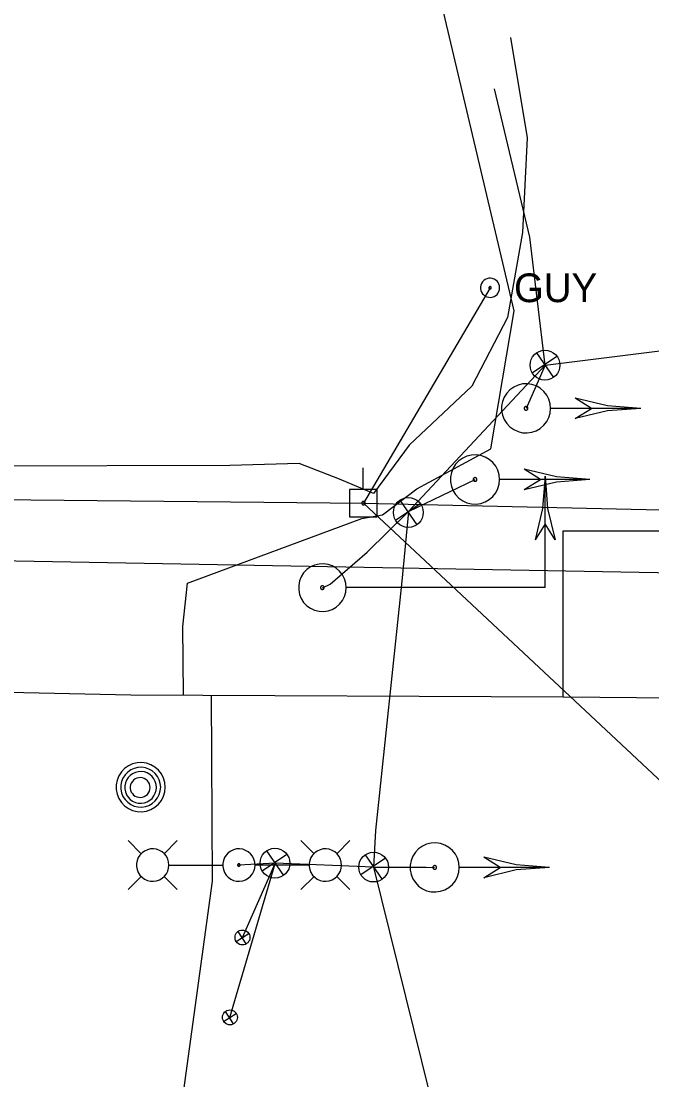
# Model space of a CAD drawing. Extents: x 600849 to 606371, y 330010 to 403088.
# Drawn here: x 604922.6 to 605007.3, y 349901.2 to 350043.3 of the extents above; entities that cross this region are included whole.
import ezdxf

# ---------------------------------------------------------------- set-up
doc = ezdxf.new("R2010")
doc.units = 0
for name, color, linetype in [('E_LTG', 7, 'Continuous'), ('E_LTG_CID', 7, 'Continuous'), ('E_SIG', 7, 'Continuous'), ('E_SIG_Conduit', 7, 'Continuous'), ('E_UTL_E_UG', 7, 'Continuous'), ('E_UTL_EGuyWire', 7, 'Continuous'), ('E_UTL_EPowerPole', 7, 'Continuous'), ('E_UTL_G_UG', 7, 'Continuous'), ('E_UTL_Loop_UG', 7, 'Continuous'), ('E_UTL_MH', 7, 'Continuous'), ('E_UTL_Overhead', 7, 'Continuous'), ('E_UTL_SAN_UG', 7, 'Continuous'), ('E_UTL_TV_UG', 7, 'Continuous')]:
    doc.layers.add(name, color=color, linetype=linetype)

# ---------------------------------------------------------------- blocks, each defined once
blk = doc.blocks.new('_U350')
at = {"layer": 'E_SIG'}
for p, q in [((0, 6.1), (0, -6.1)), ((-6.09, 0.4), (6.1, 0.4))]:
    blk.add_line(p, q, dxfattribs=at)
blk.add_circle((0, 0.01), 6.1, dxfattribs=at)
blk = doc.blocks.new('_U351')
at = {"layer": 'E_SIG'}
for p, q in [((0, 6.1), (0, -6.1)), ((-6.09, 0.4), (6.1, 0.4))]:
    blk.add_line(p, q, dxfattribs=at)
blk.add_circle((0, 0.01), 6.1, dxfattribs=at)
blk = doc.blocks.new('_U358')
at = {"layer": 'E_SIG'}
for p, q in [((0, 6.1), (0, -6.1)), ((-6.09, 0.4), (6.1, 0.4))]:
    blk.add_line(p, q, dxfattribs=at)
blk.add_circle((0, 0.01), 6.1, dxfattribs=at)
blk = doc.blocks.new('_U359')
at = {"layer": 'E_SIG'}
for p, q in [((0, 6.1), (0, -6.1)), ((-6.09, 0.4), (6.1, 0.4))]:
    blk.add_line(p, q, dxfattribs=at)
blk.add_circle((0, 0.01), 6.1, dxfattribs=at)
blk = doc.blocks.new('_U360')
at = {"layer": 'E_SIG'}
for p, q in [((-6.09, 0.4), (6.1, 0.4)), ((0, 6.1), (0, -6.1))]:
    blk.add_line(p, q, dxfattribs=at)
blk.add_circle((0, 0.01), 6.1, dxfattribs=at)
blk = doc.blocks.new('_U361')
at = {"layer": 'E_SIG'}
for p, q in [((-6.09, 0.4), (6.1, 0.4)), ((0, 6.1), (0, -6.1))]:
    blk.add_line(p, q, dxfattribs=at)
blk.add_circle((0, 0.01), 6.1, dxfattribs=at)

msp = doc.modelspace()

# ---------------------------------------------------------------- linework, layer by layer
at = {"layer": 'E_LTG'}
for points in [[(604938.74, 349931.53), (604936.97, 349933.3)], [(604941.79, 349931.53), (604943.57, 349933.3)], [(604961.92, 349931.53), (604960.14, 349933.3)], [(604964.96, 349931.53), (604966.74, 349933.3)], [(604942.44, 349930), (604942.4, 349930.42), (604942.29, 349930.81), (604942.1, 349931.18), (604941.84, 349931.5), (604941.53, 349931.78), (604941.17, 349931.98), (604940.78, 349932.12), (604940.37, 349932.18), (604939.96, 349932.16), (604939.56, 349932.06), (604939.18, 349931.89), (604938.84, 349931.65), (604938.56, 349931.35), (604938.33, 349931), (604938.18, 349930.62), (604938.1, 349930.21), (604938.1, 349929.8), (604938.18, 349929.39), (604938.33, 349929.01), (604938.56, 349928.66), (604938.84, 349928.36), (604939.18, 349928.12), (604939.56, 349927.95), (604939.96, 349927.85), (604940.37, 349927.83), (604940.78, 349927.89), (604941.17, 349928.02), (604941.53, 349928.23), (604941.84, 349928.5), (604942.1, 349928.83), (604942.29, 349929.19), (604942.4, 349929.59), (604942.44, 349930)], [(604954.01, 349930), (604953.97, 349930.41), (604953.85, 349930.81), (604953.66, 349931.18), (604953.41, 349931.5), (604953.1, 349931.78), (604952.74, 349931.98), (604952.35, 349932.12), (604951.94, 349932.18), (604951.52, 349932.16), (604951.12, 349932.06), (604950.75, 349931.89), (604950.41, 349931.65), (604950.12, 349931.35), (604949.9, 349931), (604949.75, 349930.62), (604949.67, 349930.21), (604949.67, 349929.8), (604949.75, 349929.39), (604949.9, 349929.01), (604950.12, 349928.66), (604950.41, 349928.36), (604950.75, 349928.12), (604951.12, 349927.95), (604951.52, 349927.85), (604951.94, 349927.83), (604952.35, 349927.89), (604952.74, 349928.02), (604953.1, 349928.23), (604953.41, 349928.5), (604953.66, 349928.83), (604953.85, 349929.19), (604953.97, 349929.59), (604954.01, 349930)], [(604965.61, 349930), (604965.57, 349930.41), (604965.46, 349930.81), (604965.27, 349931.18), (604965.01, 349931.5), (604964.7, 349931.78), (604964.34, 349931.98), (604963.95, 349932.12), (604963.54, 349932.18), (604963.13, 349932.16), (604962.73, 349932.06), (604962.35, 349931.89), (604962.01, 349931.65), (604961.73, 349931.35), (604961.5, 349931), (604961.35, 349930.62), (604961.27, 349930.21), (604961.27, 349929.8), (604961.35, 349929.39), (604961.5, 349929.01), (604961.73, 349928.66), (604962.01, 349928.36), (604962.35, 349928.12), (604962.73, 349927.95), (604963.13, 349927.85), (604963.54, 349927.83), (604963.95, 349927.89), (604964.34, 349928.02), (604964.7, 349928.23), (604965.01, 349928.5), (604965.27, 349928.83), (604965.46, 349929.19), (604965.57, 349929.59), (604965.61, 349930)], [(604942.48, 349930), (604949.66, 349930)], [(604952, 349930), (604952, 349930.03), (604951.99, 349930.06), (604951.97, 349930.09), (604951.95, 349930.12), (604951.93, 349930.14), (604951.9, 349930.15), (604951.87, 349930.16), (604951.84, 349930.17), (604951.81, 349930.17), (604951.78, 349930.16), (604951.75, 349930.15), (604951.73, 349930.13), (604951.7, 349930.11), (604951.69, 349930.08), (604951.67, 349930.05), (604951.67, 349930.02), (604951.67, 349929.99), (604951.67, 349929.96), (604951.69, 349929.93), (604951.7, 349929.9), (604951.73, 349929.88), (604951.75, 349929.86), (604951.78, 349929.85), (604951.81, 349929.84), (604951.84, 349929.84), (604951.87, 349929.84), (604951.9, 349929.85), (604951.93, 349929.87), (604951.95, 349929.89), (604951.97, 349929.91), (604951.99, 349929.94), (604952, 349929.97), (604952, 349930)], [(604961.22, 349930), (604954.05, 349930)], [(604938.74, 349928.48), (604936.97, 349926.7)], [(604941.79, 349928.48), (604943.57, 349926.7)], [(604961.92, 349928.48), (604960.14, 349926.7)], [(604964.96, 349928.48), (604966.74, 349926.7)]]:
    msp.add_lwpolyline(points, dxfattribs=at)
at = {"layer": 'E_LTG_CID'}
msp.add_lwpolyline([(604956.7, 349930.25), (604951.83, 349930)], dxfattribs=at)
at = {"layer": 'E_SIG'}
for points in [[(604993.68, 349991.33), (604993.62, 349991.95), (604993.44, 349992.56), (604993.15, 349993.11), (604992.76, 349993.61), (604992.29, 349994.02), (604991.75, 349994.33), (604991.15, 349994.54), (604990.53, 349994.63), (604989.91, 349994.6), (604989.3, 349994.45), (604988.73, 349994.19), (604988.21, 349993.82), (604987.78, 349993.37), (604987.44, 349992.84), (604987.21, 349992.26), (604987.09, 349991.64), (604987.09, 349991.02), (604987.21, 349990.4), (604987.44, 349989.82), (604987.78, 349989.29), (604988.21, 349988.84), (604988.73, 349988.47), (604989.3, 349988.21), (604989.91, 349988.06), (604990.53, 349988.03), (604991.15, 349988.12), (604991.75, 349988.33), (604992.29, 349988.64), (604992.76, 349989.05), (604993.15, 349989.55), (604993.44, 349990.1), (604993.62, 349990.7), (604993.68, 349991.33)], [(604999.18, 349991.33), (604996.98, 349992.71)], [(605005.78, 349991.33), (605001.32, 349991.68), (604996.98, 349992.7)], [(604990.63, 349991.33), (604990.62, 349991.38), (604990.61, 349991.42), (604990.59, 349991.47), (604990.56, 349991.5), (604990.52, 349991.54), (604990.48, 349991.56), (604990.44, 349991.57), (604990.39, 349991.58), (604990.34, 349991.58), (604990.29, 349991.57), (604990.25, 349991.55), (604990.21, 349991.52), (604990.18, 349991.49), (604990.15, 349991.45), (604990.13, 349991.4), (604990.12, 349991.35), (604990.12, 349991.31), (604990.13, 349991.26), (604990.15, 349991.21), (604990.18, 349991.17), (604990.21, 349991.14), (604990.25, 349991.11), (604990.29, 349991.09), (604990.34, 349991.08), (604990.39, 349991.08), (604990.44, 349991.08), (604990.48, 349991.1), (604990.52, 349991.12), (604990.56, 349991.16), (604990.59, 349991.19), (604990.61, 349991.24), (604990.62, 349991.28), (604990.63, 349991.33)], [(605005.78, 349991.33), (604993.73, 349991.33)], [(605005.78, 349991.33), (605001.32, 349990.98), (604996.98, 349989.95)], [(604996.98, 349989.96), (604999.18, 349991.33)], [(604986.83, 349981.78), (604986.77, 349982.4), (604986.59, 349983.01), (604986.3, 349983.56), (604985.92, 349984.06), (604985.44, 349984.47), (604984.9, 349984.78), (604984.3, 349984.99), (604983.68, 349985.07), (604983.06, 349985.04), (604982.45, 349984.9), (604981.88, 349984.64), (604981.37, 349984.27), (604980.93, 349983.82), (604980.59, 349983.29), (604980.36, 349982.71), (604980.24, 349982.09), (604980.24, 349981.46), (604980.36, 349980.85), (604980.59, 349980.27), (604980.93, 349979.74), (604981.37, 349979.28), (604981.88, 349978.92), (604982.45, 349978.66), (604983.06, 349978.51), (604983.68, 349978.48), (604984.3, 349978.57), (604984.9, 349978.78), (604985.44, 349979.09), (604985.92, 349979.5), (604986.3, 349979.99), (604986.59, 349980.55), (604986.77, 349981.15), (604986.83, 349981.78)], [(604998.93, 349981.78), (604994.47, 349982.12), (604990.13, 349983.15)], [(604992.33, 349981.78), (604990.13, 349983.15)], [(604992.94, 349982.2), (604992.6, 349977.88), (604991.6, 349973.66)], [(604992.94, 349967.26), (604992.94, 349982.2)], [(604992.94, 349982.2), (604993.27, 349977.88), (604994.27, 349973.66)], [(604983.78, 349981.78), (604983.77, 349981.83), (604983.76, 349981.87), (604983.74, 349981.91), (604983.71, 349981.95), (604983.67, 349981.98), (604983.63, 349982.01), (604983.59, 349982.02), (604983.54, 349982.03), (604983.49, 349982.03), (604983.44, 349982.02), (604983.4, 349982), (604983.36, 349981.97), (604983.33, 349981.93), (604983.3, 349981.89), (604983.28, 349981.85), (604983.28, 349981.8), (604983.28, 349981.75), (604983.28, 349981.71), (604983.3, 349981.66), (604983.33, 349981.62), (604983.36, 349981.59), (604983.4, 349981.56), (604983.44, 349981.54), (604983.49, 349981.53), (604983.54, 349981.53), (604983.59, 349981.53), (604983.63, 349981.55), (604983.67, 349981.57), (604983.71, 349981.6), (604983.74, 349981.64), (604983.76, 349981.68), (604983.77, 349981.73), (604983.78, 349981.78)], [(604998.93, 349981.78), (604986.88, 349981.78)], [(604998.93, 349981.78), (604994.47, 349981.43), (604990.13, 349980.4)], [(604990.13, 349980.41), (604992.33, 349981.78)], [(604992.94, 349975.8), (604991.6, 349973.66)], [(604994.27, 349973.66), (604992.94, 349975.8)], [(604966.25, 349967.25), (604966.19, 349967.86), (604966.02, 349968.44), (604965.74, 349968.99), (604965.36, 349969.46), (604964.9, 349969.86), (604964.37, 349970.17), (604963.8, 349970.37), (604963.2, 349970.45), (604962.59, 349970.42), (604962, 349970.28), (604961.44, 349970.03), (604960.95, 349969.68), (604960.53, 349969.23), (604960.2, 349968.72), (604959.97, 349968.16), (604959.86, 349967.56), (604959.86, 349966.95), (604959.97, 349966.35), (604960.2, 349965.79), (604960.53, 349965.27), (604960.95, 349964.83), (604961.44, 349964.48), (604962, 349964.23), (604962.59, 349964.08), (604963.2, 349964.06), (604963.8, 349964.14), (604964.37, 349964.34), (604964.9, 349964.65), (604965.36, 349965.04), (604965.74, 349965.52), (604966.02, 349966.06), (604966.19, 349966.65), (604966.25, 349967.25)], [(604963.29, 349967.25), (604963.28, 349967.3), (604963.27, 349967.35), (604963.25, 349967.39), (604963.22, 349967.42), (604963.19, 349967.45), (604963.15, 349967.48), (604963.1, 349967.49), (604963.06, 349967.5), (604963.01, 349967.5), (604962.96, 349967.49), (604962.92, 349967.47), (604962.88, 349967.44), (604962.85, 349967.41), (604962.83, 349967.37), (604962.81, 349967.32), (604962.8, 349967.28), (604962.8, 349967.23), (604962.81, 349967.19), (604962.83, 349967.14), (604962.85, 349967.1), (604962.88, 349967.07), (604962.92, 349967.04), (604962.96, 349967.02), (604963.01, 349967.01), (604963.06, 349967.01), (604963.1, 349967.02), (604963.15, 349967.03), (604963.19, 349967.05), (604963.22, 349967.09), (604963.25, 349967.12), (604963.27, 349967.16), (604963.28, 349967.21), (604963.29, 349967.25)], [(604992.94, 349967.26), (604966.3, 349967.26)], [(604985.46, 349967.26), (604985.46, 349967.26)], [(604981.41, 349929.68), (604981.35, 349930.31), (604981.18, 349930.91), (604980.89, 349931.47), (604980.5, 349931.96), (604980.03, 349932.37), (604979.48, 349932.68), (604978.89, 349932.89), (604978.27, 349932.98), (604977.64, 349932.95), (604977.03, 349932.8), (604976.46, 349932.54), (604975.95, 349932.18), (604975.52, 349931.72), (604975.18, 349931.19), (604974.95, 349930.61), (604974.83, 349930), (604974.83, 349929.37), (604974.95, 349928.75), (604975.18, 349928.17), (604975.52, 349927.64), (604975.95, 349927.19), (604976.46, 349926.82), (604977.03, 349926.56), (604977.64, 349926.42), (604978.27, 349926.39), (604978.89, 349926.48), (604979.48, 349926.68), (604980.03, 349926.99), (604980.5, 349927.41), (604980.89, 349927.9), (604981.18, 349928.46), (604981.35, 349929.06), (604981.41, 349929.68)], [(604993.51, 349929.68), (604989.06, 349930.03), (604984.71, 349931.06)], [(604986.91, 349929.68), (604984.71, 349931.06)], [(604978.37, 349929.68), (604978.36, 349929.73), (604978.35, 349929.78), (604978.33, 349929.82), (604978.3, 349929.86), (604978.26, 349929.89), (604978.22, 349929.91), (604978.17, 349929.93), (604978.13, 349929.93), (604978.08, 349929.93), (604978.03, 349929.92), (604977.99, 349929.9), (604977.95, 349929.87), (604977.92, 349929.84), (604977.89, 349929.8), (604977.87, 349929.75), (604977.86, 349929.71), (604977.86, 349929.66), (604977.87, 349929.61), (604977.89, 349929.57), (604977.92, 349929.53), (604977.95, 349929.49), (604977.99, 349929.46), (604978.03, 349929.44), (604978.08, 349929.43), (604978.13, 349929.43), (604978.17, 349929.44), (604978.22, 349929.45), (604978.26, 349929.48), (604978.3, 349929.51), (604978.33, 349929.55), (604978.35, 349929.59), (604978.36, 349929.63), (604978.37, 349929.68)], [(604993.51, 349929.68), (604981.47, 349929.68)], [(604993.51, 349929.68), (604989.06, 349929.34), (604984.71, 349928.31)], [(604984.71, 349928.31), (604986.91, 349929.68)]]:
    msp.add_lwpolyline(points, dxfattribs=at)
at = {"layer": 'E_SIG_Conduit'}
for points in [[(604992.92, 349997.12), (605041.26, 350003.17), (605045.68, 350004), (605067.59, 350003.14), (605103.15, 349993.06), (605106.99, 349992.73)], [(604963.04, 349967.25), (604964.1, 349967.7), (604969.04, 349972.01), (604974.59, 349977.47), (604992.92, 349997.12)], [(604992.92, 349997.12), (604990.38, 349991.33)], [(604974.59, 349977.47), (604983.53, 349981.78)], [(604974.59, 349977.47), (604973.7, 349968.11), (604970.17, 349934.65), (604969.92, 349929.73)], [(604969.92, 349929.73), (604956.7, 349930.25)], [(604969.92, 349929.73), (604985.98, 349864.78), (604987.57, 349858.81)], [(604969.92, 349929.73), (604976.98, 349929.73), (604978.11, 349929.68)]]:
    msp.add_lwpolyline(points, dxfattribs=at)
at = {"layer": 'E_UTL_E_UG'}
msp.add_lwpolyline([(604992.92, 349997.12), (604990.88, 350014.31), (604986.13, 350034.21)], dxfattribs=at)
at = {"layer": 'E_UTL_EGuyWire'}
msp.add_line((604985.55, 350007.51), (604968.56, 349978.6), dxfattribs=at)
for points in [[(604986.83, 350007.51), (604986.81, 350007.76), (604986.74, 350007.99), (604986.63, 350008.21), (604986.48, 350008.4), (604986.3, 350008.56), (604986.08, 350008.68), (604985.85, 350008.76), (604985.61, 350008.8), (604985.37, 350008.79), (604985.13, 350008.73), (604984.91, 350008.63), (604984.71, 350008.48), (604984.54, 350008.31), (604984.41, 350008.1), (604984.32, 350007.88), (604984.27, 350007.64), (604984.27, 350007.39), (604984.32, 350007.15), (604984.41, 350006.93), (604984.54, 350006.72), (604984.71, 350006.55), (604984.91, 350006.4), (604985.13, 350006.3), (604985.37, 350006.24), (604985.61, 350006.23), (604985.85, 350006.27), (604986.08, 350006.35), (604986.3, 350006.47), (604986.48, 350006.63), (604986.63, 350006.82), (604986.74, 350007.04), (604986.81, 350007.27), (604986.83, 350007.51)], [(604985.71, 350007.51), (604985.71, 350007.55), (604985.7, 350007.57), (604985.69, 350007.6), (604985.67, 350007.63), (604985.64, 350007.65), (604985.62, 350007.66), (604985.59, 350007.67), (604985.56, 350007.68), (604985.53, 350007.67), (604985.5, 350007.67), (604985.47, 350007.65), (604985.45, 350007.64), (604985.42, 350007.61), (604985.41, 350007.59), (604985.4, 350007.56), (604985.39, 350007.53), (604985.39, 350007.5), (604985.4, 350007.47), (604985.41, 350007.44), (604985.42, 350007.42), (604985.45, 350007.39), (604985.47, 350007.38), (604985.5, 350007.36), (604985.53, 350007.36), (604985.56, 350007.35), (604985.59, 350007.36), (604985.62, 350007.37), (604985.64, 350007.38), (604985.67, 350007.4), (604985.69, 350007.43), (604985.7, 350007.46), (604985.71, 350007.48), (604985.71, 350007.51)]]:
    msp.add_lwpolyline(points, dxfattribs=at)
at = {"layer": 'E_UTL_EPowerPole'}
for points in [[(604968.53, 349980.44), (604968.53, 349983.35)], [(604970.38, 349980.44), (604966.69, 349980.44)], [(604966.69, 349980.44), (604966.69, 349976.75)], [(604970.38, 349976.75), (604970.38, 349980.44)], [(604968.8, 349978.6), (604968.8, 349978.65), (604968.79, 349978.69), (604968.76, 349978.73), (604968.74, 349978.77), (604968.7, 349978.8), (604968.66, 349978.82), (604968.62, 349978.83), (604968.58, 349978.84), (604968.53, 349978.84), (604968.49, 349978.83), (604968.44, 349978.81), (604968.41, 349978.78), (604968.38, 349978.75), (604968.35, 349978.71), (604968.34, 349978.67), (604968.33, 349978.62), (604968.33, 349978.58), (604968.34, 349978.53), (604968.35, 349978.49), (604968.38, 349978.45), (604968.41, 349978.42), (604968.44, 349978.39), (604968.49, 349978.38), (604968.53, 349978.36), (604968.58, 349978.36), (604968.62, 349978.37), (604968.66, 349978.38), (604968.7, 349978.41), (604968.74, 349978.44), (604968.76, 349978.47), (604968.79, 349978.51), (604968.8, 349978.56), (604968.8, 349978.6)], [(604966.69, 349976.75), (604970.38, 349976.75)]]:
    msp.add_lwpolyline(points, dxfattribs=at)
at = {"layer": 'E_UTL_G_UG'}
for points in [[(604944.96, 349967.84), (604968.33, 349976.55), (604971.11, 349977.02), (604975.73, 349980.5), (604985.67, 349985.89), (604988.78, 350004.44), (604973.16, 350070.59)], [(604995.37, 349952.58), (604995.37, 349974.87), (605039.42, 349974.87)], [(604944.41, 349952.84), (604944.33, 349962.04), (604944.96, 349967.84)], [(604797.56, 349955.68), (604807.59, 349955.39), (604836.44, 349954.33), (604859.25, 349954.54), (604937.34, 349952.88), (604995.37, 349952.58), (605059.43, 349951.99), (605132.59, 349953.68), (605169.29, 349952.69)], [(604939.48, 349844.93), (604938.89, 349859.3), (604948.31, 349927.83), (604948.15, 349952.82)]]:
    msp.add_lwpolyline(points, dxfattribs=at)
at = {"layer": 'E_UTL_Loop_UG'}
for p in [(604950.63, 349909.55), (604952.32, 349920.28)]:
    msp.add_line(p, (604956.69, 349930.2), dxfattribs=at)
at = {"layer": 'E_UTL_MH'}
for points in [[(604941.95, 349940.46), (604941.89, 349941.09), (604941.72, 349941.69), (604941.43, 349942.25), (604941.04, 349942.74), (604940.57, 349943.15), (604940.02, 349943.46), (604939.43, 349943.67), (604938.81, 349943.76), (604938.18, 349943.73), (604937.57, 349943.58), (604937, 349943.32), (604936.49, 349942.96), (604936.06, 349942.5), (604935.72, 349941.97), (604935.49, 349941.39), (604935.37, 349940.78), (604935.37, 349940.15), (604935.49, 349939.53), (604935.72, 349938.95), (604936.06, 349938.42), (604936.49, 349937.97), (604937, 349937.6), (604937.57, 349937.34), (604938.18, 349937.2), (604938.81, 349937.17), (604939.43, 349937.26), (604940.02, 349937.46), (604940.57, 349937.77), (604941.04, 349938.19), (604941.43, 349938.68), (604941.72, 349939.24), (604941.89, 349939.84), (604941.95, 349940.46)], [(604941.34, 349940.46), (604941.29, 349940.96), (604941.15, 349941.45), (604940.91, 349941.91), (604940.6, 349942.31), (604940.21, 349942.64), (604939.77, 349942.89), (604939.29, 349943.06), (604938.79, 349943.13), (604938.28, 349943.11), (604937.79, 349942.99), (604937.32, 349942.78), (604936.91, 349942.48), (604936.56, 349942.11), (604936.28, 349941.68), (604936.09, 349941.21), (604936, 349940.71), (604936, 349940.2), (604936.09, 349939.7), (604936.28, 349939.23), (604936.56, 349938.8), (604936.91, 349938.43), (604937.32, 349938.14), (604937.79, 349937.93), (604938.28, 349937.81), (604938.79, 349937.78), (604939.29, 349937.86), (604939.77, 349938.02), (604940.21, 349938.28), (604940.6, 349938.61), (604940.91, 349939.01), (604941.15, 349939.46), (604941.29, 349939.95), (604941.34, 349940.46)], [(604940.77, 349940.43), (604940.74, 349940.83), (604940.62, 349941.22), (604940.44, 349941.58), (604940.19, 349941.9), (604939.88, 349942.16), (604939.53, 349942.37), (604939.15, 349942.5), (604938.75, 349942.56), (604938.34, 349942.54), (604937.95, 349942.44), (604937.58, 349942.27), (604937.25, 349942.04), (604936.97, 349941.75), (604936.75, 349941.4), (604936.6, 349941.03), (604936.53, 349940.63), (604936.53, 349940.23), (604936.6, 349939.83), (604936.75, 349939.45), (604936.97, 349939.11), (604937.25, 349938.82), (604937.58, 349938.59), (604937.95, 349938.42), (604938.34, 349938.32), (604938.75, 349938.3), (604939.15, 349938.36), (604939.53, 349938.49), (604939.88, 349938.7), (604940.19, 349938.96), (604940.44, 349939.28), (604940.62, 349939.64), (604940.74, 349940.03), (604940.77, 349940.43)], [(604939.92, 349940.41), (604939.89, 349940.67), (604939.82, 349940.91), (604939.71, 349941.13), (604939.55, 349941.33), (604939.36, 349941.5), (604939.14, 349941.63), (604938.9, 349941.71), (604938.65, 349941.74), (604938.4, 349941.73), (604938.15, 349941.67), (604937.92, 349941.57), (604937.71, 349941.42), (604937.54, 349941.24), (604937.4, 349941.02), (604937.31, 349940.79), (604937.26, 349940.54), (604937.26, 349940.29), (604937.31, 349940.04), (604937.4, 349939.8), (604937.54, 349939.59), (604937.71, 349939.41), (604937.92, 349939.26), (604938.15, 349939.16), (604938.4, 349939.1), (604938.65, 349939.08), (604938.9, 349939.12), (604939.14, 349939.2), (604939.36, 349939.33), (604939.55, 349939.49), (604939.71, 349939.69), (604939.82, 349939.92), (604939.89, 349940.16), (604939.92, 349940.41)]]:
    msp.add_lwpolyline(points, dxfattribs=at)
at = {"layer": 'E_UTL_Overhead'}
for points in [[(603181.1, 350033.93), (603327.14, 350030.65), (603489.53, 350051.02), (603697.71, 350051.22), (603796.19, 350042.83), (603984.49, 350028.4), (604130.29, 350016.64), (604350.17, 349999.98), (604453.05, 349992.41), (604555.19, 349985.21), (604652.23, 349982.52), (604745.22, 349980.5), (604854.74, 349979.72), (604968.56, 349978.6), (605154.01, 349974.42)], [(604968.56, 349978.6), (605140.32, 349817.89)]]:
    msp.add_lwpolyline(points, dxfattribs=at)
at = {"layer": 'E_UTL_SAN_UG'}
msp.add_line((604736.58, 349974.22), (605034.55, 349968.79), dxfattribs=at)
at = {"layer": 'E_UTL_TV_UG'}
msp.add_lwpolyline([(604988.28, 350041.13), (604990.53, 350027.64), (604989.92, 350014.96), (604987.9, 350003.51), (604983.08, 349994.32), (604974.67, 349986.39), (604969.91, 349979.91), (604965.32, 349981.81), (604959.93, 349983.92), (604950.62, 349983.67), (604917.59, 349983.57)], dxfattribs=at)

# ---------------------------------------------------------------- block references
at = {"layer": 'E_SIG_Conduit'}
for name, p, xscale, yscale, rotation in [('_U351', (604992.92, 349997.12), 0.32808333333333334, 0.3280833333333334, 34.193210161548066), ('_U350', (604974.58, 349977.34), 0.32808333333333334, 0.3280833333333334, 34.193210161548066), ('_U359', (604956.68, 349930.25), 0.32808333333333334, 0.3280833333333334, 34.193210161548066), ('_U358', (604969.92, 349929.73), 0.32808333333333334, 0.3280833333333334, 34.193210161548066), ('_U361', (604952.32, 349920.28), 0.16404166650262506, 0.16404166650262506, 122.69997330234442), ('_U360', (604950.63, 349909.55), 0.16404166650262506, 0.16404166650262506, 122.69997330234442)]:
    msp.add_blockref(name, p, dxfattribs=dict(at, xscale=xscale, yscale=yscale, rotation=rotation))

# ---------------------------------------------------------------- texts
at = {"layer": 'E_UTL_EGuyWire'}
msp.add_text('GUY', height=3.85, dxfattribs=at).set_placement((604988.76, 350005.59))

doc.saveas('drawing.dxf')
